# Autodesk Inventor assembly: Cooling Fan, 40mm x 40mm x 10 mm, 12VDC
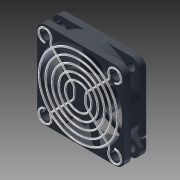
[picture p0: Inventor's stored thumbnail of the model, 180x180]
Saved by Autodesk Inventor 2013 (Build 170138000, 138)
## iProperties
Company: Autodesk Inc.
Created: 2005-12
Part Number: Cooling Fan, 40mm x 40mm x 10 mm, 12VDC
Document SubType Name: Assembly
Designer: Autodesk Inc.
Mass: 7.1514 g
Surface Area: 82.7652 cm^2
Volume: 7.1514 cm^3
Density: 1 g/cm^3
Title: Personal Computer
Author: Autodesk Inc.
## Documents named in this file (3)
- Z:\_DATEN\Personal Computer\Motherboard\Processor Fan\Cooling Fan, 40mm x 40mm x 10 mm, 12VDC.iam
- Z:\_DATEN\Personal Computer\Motherboard\Processor Fan\Cooling Fan, 40mm x 40mm x 10 mm, 12VDC.ipt
- Z:\_DATEN\Personal Computer\Motherboard\Processor Fan\Fan Guard, 40mm.ipt
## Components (2 placed, 2 different names)
1. Cooling Fan, 40mm x 40mm x 10 mm, 12VDC:1 — Mate:2, Mate:3, Tangent:1
2. Fan Guard, 40mm:1 — Mate:2, Mate:3, Tangent:1
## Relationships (3: Mate 2, Tangent 1)
- Mate:2: Cooling Fan, 40mm x 40mm x 10 mm, 12VDC:1 ↔ Fan Guard, 40mm:1
- Mate:3: Cooling Fan, 40mm x 40mm x 10 mm, 12VDC:1 ↔ Fan Guard, 40mm:1
- Tangent:1: Cooling Fan, 40mm x 40mm x 10 mm, 12VDC:1 ↔ Fan Guard, 40mm:1
